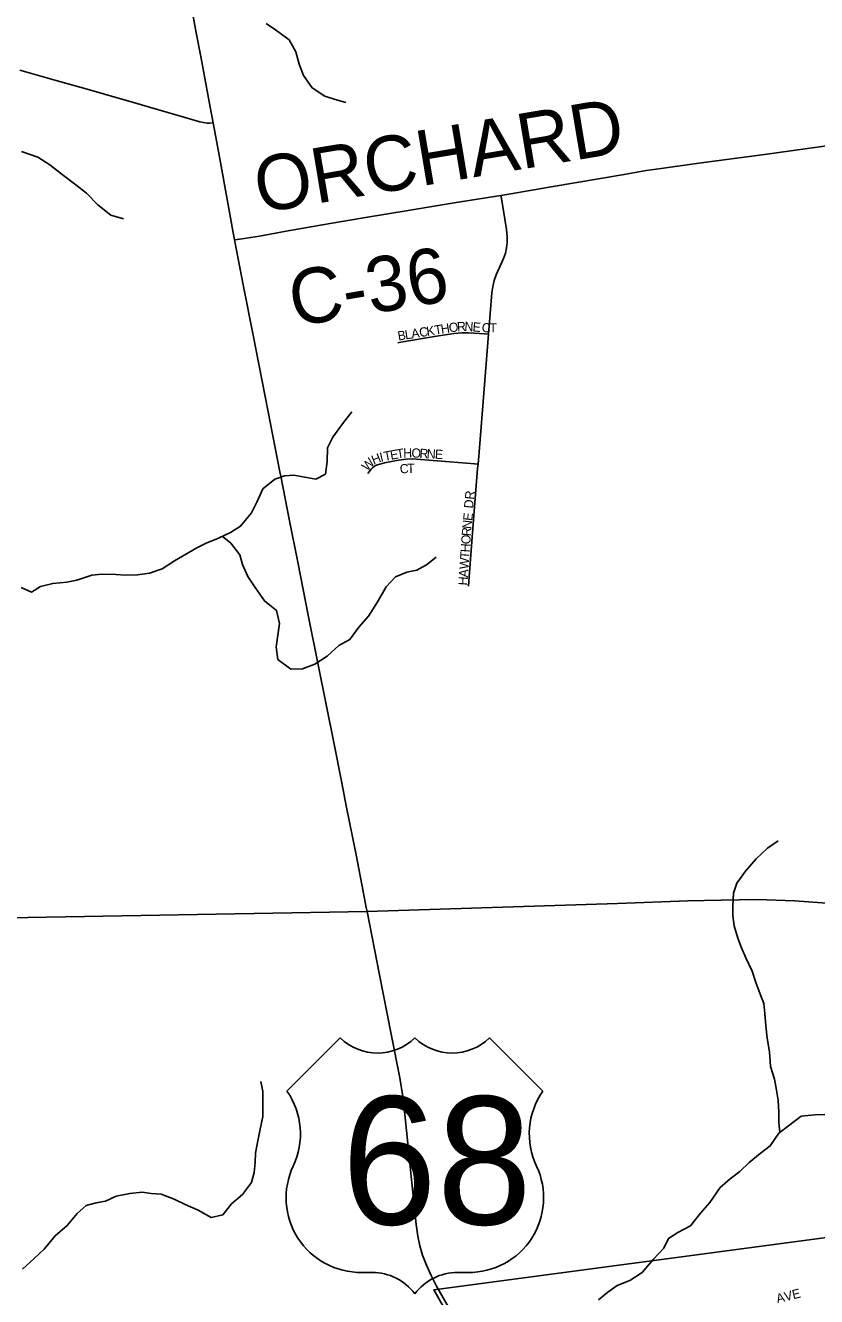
# Model space of a CAD drawing. Extents: x 1442749 to 1756758, y 235267 to 677782.
# Drawn here: x 1589318 to 1593624, y 534274 to 541188 of the extents above; entities that cross this region are included whole.
import ezdxf

# ---------------------------------------------------------------- set-up
doc = ezdxf.new("R2010")
doc.units = 0
for name, color, linetype in [('GM_P_State_Alignment', 7, 'Continuous'), ('GM_X_City_Street_Text', 7, 'Continuous'), ('GM_X_Corporation', 7, 'Continuous'), ('GM_X_County_Road', 7, 'Continuous'), ('GM_X_County_Road_Text', 7, 'Continuous'), ('GM_X_Minor_River', 7, 'Continuous'), ('GM_X_Township_Subdivision', 7, 'Continuous'), ('GM_X_Township_Subdivision_Text', 7, 'Continuous'), ('GM_X_US_Location', 7, 'Continuous'), ('GM_X_US_Route', 7, 'Continuous'), ('GM_X_US_Shield', 7, 'Continuous')]:
    doc.layers.add(name, color=color, linetype=linetype)

msp = doc.modelspace()

# ---------------------------------------------------------------- linework, layer by layer
at = {"layer": 'GM_P_State_Alignment'}
for points in [[(1591177.3, 536368.3), (1592540.6, 536412.7), (1592922.9, 536426.3), (1593101.8, 536430.5), (1593301.6, 536434.6), (1593503.4, 536426.3), (1593705.2, 536411.8), (1593900.7, 536393), (1594100.5, 536366), (1594300.2, 536330.6), (1594491.6, 536289), (1594687.2, 536243.2), (1594882.7, 536187.1), (1595024.2, 536143.4), (1595190.6, 536085.1), (1595341.4, 536032.9), (1596060.7, 535775.7), (1599323.3, 534630.8), (1600098.2, 534456.7), (1600484.1, 534379), (1600863.9, 534361), (1601641.5, 534432.8), (1602490.9, 534540.5), (1603334.8, 534713.2)], [(1586455.9, 536285.6), (1591177.3, 536368.3)]]:
    msp.add_lwpolyline(points, dxfattribs=at)
at = {"layer": 'GM_X_Corporation'}
msp.add_lwpolyline([(1591592.8, 534218.7), (1591541.7, 534311.9), (1593692.6, 534596.7), (1593726.4, 535006.4), (1594301.4, 535104.8), (1594436.1, 535066.6), (1594435.7, 535026.5), (1594694.2, 534853.4), (1594736.8, 534710.6), (1594883.6, 534673.8), (1594801.6, 534407.2), (1594965.1, 534337.4), (1595254.7, 535192.4), (1595342.6, 535173.4), (1595371.9, 535287.4), (1595655.6, 535205.1), (1595677.5, 535508.1), (1595692.5, 535694.6), (1598975.5, 534553.1), (1599120.4, 534412), (1599138.1, 534392.6), (1599013, 534202.8)], dxfattribs=at)
at = {"layer": 'GM_X_County_Road'}
for points in [[(1589288.3, 540944.1), (1589477.8, 540891.3), (1589654.3, 540841.2), (1589749.3, 540814.3), (1589906.8, 540769.7), (1590180.5, 540689), (1590267, 540664.2), (1590288, 540659.9), (1590306.7, 540656.7), (1590317.5, 540655.8), (1590339.9, 540658.2)], [(1591906.3, 540264.1), (1591949.6, 540271.2), (1592179.2, 540310), (1592576.7, 540378.3), (1592696.3, 540399.1), (1592777.6, 540410.9), (1592982.3, 540438.5), (1593340, 540486.2), (1593794.8, 540549.3), (1593963.9, 540571.7), (1594243.3, 540609.8), (1594425.1, 540635.9), (1594613.5, 540661.9), (1594840.9, 540694.2), (1595360.7, 540765.5), (1595539.3, 540791), (1595961.5, 540850.2), (1596201.8, 540884.2), (1596347.8, 540904.9), (1596467.8, 540923), (1596672.8, 540949.5), (1596748, 540957.1), (1596783.4, 540957.7)], [(1590456.4, 540022.2), (1590497.5, 540028.3), (1590591.3, 540042.4), (1590736.5, 540069.1), (1590965.9, 540108.3), (1591169.7, 540142.9), (1591412.4, 540183.1), (1591651.8, 540222.7), (1591906.3, 540264.1)]]:
    msp.add_lwpolyline(points, dxfattribs=at)
at = {"layer": 'GM_X_Minor_River'}
for points in [[(1590628, 541198.4), (1590679.7, 541163.7), (1590753.2, 541110.7), (1590790.5, 541044.1), (1590807.8, 540977.7), (1590831.1, 540915.3), (1590878.4, 540848.5), (1590948, 540803.6), (1591003.9, 540784.9), (1591061.8, 540768.2)], [(1589296.9, 540501.7), (1589386.7, 540472.5), (1589450.3, 540429.7), (1589517.9, 540376.8), (1589593.4, 540321.8), (1589650.9, 540275), (1589712.3, 540212.1), (1589783.8, 540157.1), (1589851.7, 540136.3)], [(1590579, 538599.7), (1590609.9, 538667.5), (1590674.7, 538721), (1590729, 538738.4), (1590779.1, 538741.8), (1590899.1, 538720.4), (1590951.6, 538747.9), (1590960.4, 538816), (1590961.3, 538890.2), (1590992, 538948), (1591043, 539021.6), (1591093.9, 539087.2)], [(1589294.7, 538131.1), (1589350.5, 538106.4), (1589401, 538135.9), (1589467.3, 538153.2), (1589543.6, 538160.3), (1589597.8, 538171.7), (1589680.3, 538198.9), (1589734.5, 538204.3), (1589810.6, 538201.4), (1589862.7, 538198.8), (1589928.9, 538200), (1589993.1, 538209.3), (1590061.6, 538232.6), (1590130.2, 538275.9), (1590251.3, 538346.8), (1590301.7, 538372.2), (1590368.2, 538399.6), (1590434.7, 538430.9), (1590489.2, 538464.4), (1590548.2, 538537.9), (1590579, 538599.7)], [(1590389.3, 538409.5), (1590436, 538372.7), (1590485.4, 538308), (1590498.8, 538255.7), (1590528.1, 538191.2), (1590569.4, 538130.5), (1590618.7, 538057.8), (1590684.2, 538006.9), (1590701.4, 537934.5), (1590690.5, 537858.4), (1590681.9, 537808.3), (1590691.1, 537740), (1590762.6, 537687.1), (1590826.7, 537688.3), (1590893.2, 537713.7), (1590959.8, 537757), (1591024.7, 537816.4), (1591083.2, 537847.8), (1591132.1, 537915.5), (1591184.9, 537975), (1591231.9, 538048.7), (1591281, 538134.4), (1591331.8, 538190), (1591394.2, 538215.3), (1591448.4, 538224.7), (1591500.9, 538254.2), (1591553.5, 538295.7)], [(1593423.5, 535167.5), (1593419.1, 535223.8), (1593417.7, 535275.9), (1593414.5, 535342.2), (1593405.1, 535396.4), (1593393.8, 535456.7), (1593372.5, 535525.2), (1593367.5, 535605.4), (1593354.3, 535679.8), (1593347.1, 535746.1), (1593341.9, 535814.3), (1593336.5, 535868.5), (1593315.1, 535924.9), (1593293.8, 535983.3), (1593272.5, 536043.8), (1593239.3, 536116.3), (1593215.9, 536170.8), (1593194.4, 536223.2), (1593175.2, 536291.6), (1593167.8, 536345.8), (1593168.5, 536399.9), (1593171.3, 536468.1), (1593190, 536522.1), (1593236.8, 536587.7), (1593295.8, 536655.2), (1593356.6, 536712.7), (1593415.2, 536754.1)], [(1589302.7, 534422.6), (1589365.6, 534482), (1589420.3, 534531.5), (1589479.3, 534605.1), (1589546.1, 534660.5), (1589599, 534726), (1589649.6, 534769.6), (1589703.9, 534785), (1589754.1, 534792.5), (1589812.5, 534819.9), (1589886.9, 534835.1), (1589953.1, 534842.3), (1590003.1, 534835.8), (1590057.2, 534831.1), (1590127, 534804.2), (1590186.8, 534775.5), (1590258.6, 534744.6), (1590328.3, 534703.7), (1590392.6, 534719), (1590439.4, 534778.6), (1590500.1, 534830), (1590549, 534895.7), (1590563.7, 534949.7), (1590568.3, 535003.8), (1590570.9, 535053.9), (1590579.6, 535103.9), (1590594.4, 535175.9), (1590609.4, 535254), (1590611, 535390.4), (1590599.6, 535444.6)], [(1592437.5, 534256.2), (1592488.1, 534297.8), (1592538.7, 534335.3), (1592607.1, 534362.6), (1592673.8, 534406), (1592734.7, 534475.5), (1592791.6, 534537), (1592818.3, 534590.8), (1592868.8, 534622.3), (1592937.3, 534659.7), (1592992.3, 534727.2), (1593043.1, 534786.8), (1593098.2, 534868.4), (1593152.8, 534913.9), (1593205.4, 534955.4), (1593256.1, 535003), (1593316.8, 535052.4), (1593371.4, 535093.9), (1593418.3, 535163.6), (1593470.9, 535203.1), (1593539.7, 535256.5), (1593614, 535263.7), (1593668.1, 535265)]]:
    msp.add_lwpolyline(points, dxfattribs=at)
at = {"layer": 'GM_X_Township_Subdivision'}
for points in [[(1591838.5, 539508.4), (1591856.3, 539733.8), (1591861, 539765.9), (1591869.2, 539800.4), (1591880, 539830.9), (1591920, 539920.9), (1591930.1, 539949.1), (1591937, 539978.4), (1591940.5, 540008.3), (1591940.7, 540038.3), (1591936.8, 540077.9), (1591910.8, 540236.7), (1591906.3, 540264.1)], [(1591344.7, 539462.2), (1591360.9, 539464.8), (1591554.8, 539497.3), (1591651.6, 539512.5), (1591693.6, 539516.5), (1591729.2, 539516.3), (1591816.4, 539510), (1591838.5, 539508.4)], [(1591781.2, 538801.4), (1591788.7, 538889.9), (1591813.1, 539187.6), (1591838.5, 539508.4)], [(1591181.1, 538751.2), (1591200.6, 538775.4), (1591207.8, 538782.6), (1591215.9, 538789.4), (1591223.9, 538794.5), (1591234.7, 538799.1), (1591272.1, 538809), (1591348.9, 538824.5), (1591390.6, 538829.7), (1591422.9, 538830.4), (1591559.7, 538820.9), (1591742.3, 538804.9), (1591781.2, 538801.4)], [(1591728.6, 538137.7), (1591732.6, 538190), (1591753.8, 538451.6), (1591779.3, 538778.8), (1591781.2, 538801.4)]]:
    msp.add_lwpolyline(points, dxfattribs=at)
at = {"layer": 'GM_X_US_Route'}
for points in [[(1590707.8, 538737), (1590703.2, 538760.1), (1590639.9, 539087.4), (1590555.2, 539513.4), (1590504.8, 539767.7), (1590456.4, 540022.2), (1590447.3, 540070.2), (1590421, 540212.8), (1590371.8, 540483.4), (1590339.9, 540658.2), (1590324.3, 540743.9), (1590272.3, 541019.1), (1590248, 541147.7), (1590214, 541329.3)], [(1591173, 536390.6), (1591156.3, 536477.6), (1591118.2, 536677.1), (1591066, 536933.7), (1591038.2, 537076.9), (1590998.8, 537279.4), (1590911.4, 537710.4), (1590859.6, 537970.9), (1590800.3, 538269.5), (1590756.1, 538494.3), (1590707.8, 538737)], [(1591795.4, 533957.1), (1591766.8, 533998), (1591707.4, 534084.4), (1591655.8, 534162.5), (1591606.6, 534242.5), (1591555.8, 534330.5), (1591525.7, 534388.4), (1591500.2, 534444.9), (1591479.4, 534499.8), (1591464.4, 534549.7), (1591452.9, 534603.7), (1591444, 534666.8), (1591432.5, 534785.5), (1591408.7, 535019), (1591385.7, 535248.4), (1591371.4, 535362.5), (1591356.5, 535463.6), (1591309, 535702.5), (1591245.2, 536024.9), (1591177.3, 536368.3), (1591173, 536390.6)]]:
    msp.add_lwpolyline(points, dxfattribs=at)
at = {"layer": 'GM_X_US_Shield'}
for p, q in [((1591031.5, 535681.8), (1590741.5, 535391.8)), ((1592133.6, 535391.8), (1591843.6, 535681.8)), ((1591147.5, 534405.7), (1591205.5, 534405.7)), ((1591669.6, 534405.7), (1591727.6, 534405.7))]:
    msp.add_line(p, q, dxfattribs=at)
for centre, radius, start, end in [((1591234.5, 535889), 290, 225.573, 314.427), ((1591640.6, 535889), 290, 225.573, 314.427), ((1590408.8, 535158.9), 406.1, 334.54712, 35.00093), ((1592466.3, 535158.9), 406.1, 144.99907, 205.45288), ((1591143, 534811.7), 406.1, 154.83192, 270.63826), ((1591732.1, 534811.7), 406.1, 269.36174, 25.16808), ((1591205.5, 534115.6), 290, 36.8699, 90), ((1591669.6, 534115.6), 290, 90, 143.1301)]:
    msp.add_arc(centre, radius, start, end, dxfattribs=at)

# ---------------------------------------------------------------- texts
at = {"layer": 'GM_X_City_Street_Text'}
msp.add_text('AVE', height=50, rotation=14.03073, dxfattribs=at).set_placement((1593410.9, 534237.9))
at = {"layer": 'GM_X_County_Road_Text'}
for s, rotation, p in [('ORCHARD', 9.50838, (1590591.4, 540166.4)), ('C-36', 9.51761, (1590779.7, 539549))]:
    msp.add_text(s, height=300, rotation=rotation, dxfattribs=at).set_placement(p)
at = {"layer": 'GM_X_Township_Subdivision_Text'}
for s, rotation, p in [('T', 9.02918, (1591548, 539505.8)), ('H', 9.04193, (1591582.8, 539511.3)), ('O', 8.06829, (1591626, 539518.2)), ('R', 3.64449, (1591668.5, 539524.3)), ('N', 357.11358, (1591706.6, 539526.8)), ('E', 354.69178, (1591750, 539524.6)), ('C', 357.57039, (1591800.9, 539519.9)), ('T', 359.94573, (1591842.8, 539518.2)), ('B', 9.02313, (1591348.1, 539474)), ('L', 9.02918, (1591387.2, 539480.3)), ('A', 8.99876, (1591421.9, 539485.8)), ('C', 9.04192, (1591465.4, 539492.7)), ('K', 8.99876, (1591504.5, 539498.9)), ('T', 10.77407, (1591273.3, 538819)), ('E', 10.32928, (1591307.7, 538825.6)), ('T', 9.65989, (1591342.2, 538831.9)), ('H', 1.52985, (1591375, 538837.6)), ('O', 356.93897, (1591418, 538838.8)), ('R', 356.74337, (1591461.9, 538836.5)), ('N', 356.76148, (1591501.4, 538834.2)), ('E', 356.75794, (1591545.4, 538831.7)), ('W', 46.0105, (1591178.2, 538760.7)), ('H', 21.48479, (1591213.2, 538798.8)), ('I', 12.78488, (1591252.3, 538814.3)), ('C', 4.86245, (1591357.7, 538750.5)), ('T', 1.03815, (1591396.3, 538753.9)), ('DR', 83.99338, (1591753.8, 538559.3)), ('E', 83.67489, (1591749.2, 538491.5)), ('R', 85.72053, (1591741.9, 538408.7)), ('N', 84.24155, (1591744.8, 538447.8)), ('O', 85.95176, (1591738.8, 538364.9)), ('T', 85.9533, (1591733.2, 538285.8)), ('H', 85.97317, (1591735.7, 538321)), ('W', 85.96228, (1591729.2, 538228.8)), ('H', 85.95176, (1591723, 538141)), ('A', 85.96238, (1591726.1, 538184.9))]:
    msp.add_text(s, height=50, rotation=rotation, dxfattribs=at).set_placement(p)
at = {"layer": 'GM_X_US_Location'}
for s in ['/', '0']:
    msp.add_text(s, height=1, dxfattribs=at).set_placement((1591437.2, 535009.2))
msp.add_text('68', height=1, rotation=0.00001, dxfattribs=at).set_placement((1591230.7, 534802.3))
at = {"layer": 'GM_X_US_Shield'}
msp.add_text('68', height=696.1, dxfattribs=at).set_placement((1591039.1, 534666.7))

doc.saveas('drawing.dxf')
